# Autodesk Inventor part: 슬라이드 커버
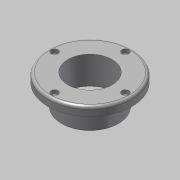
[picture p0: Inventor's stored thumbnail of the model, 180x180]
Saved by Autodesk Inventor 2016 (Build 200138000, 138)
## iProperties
Created: 2015-10
Part Number: 슬라이드 커버
Document SubType Name: Modeling
Designer: mdu
Density: 7.86 g/cm^3
Material: 강철, 연강
Mass: 633.012 g
Surface Area: 239.629 cm^2
Volume: 80.5358 cm^3
Appearance: 강철
Author: mdu
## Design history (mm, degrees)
sketch "스케치1"
  geometry: C1 r 47.5 at (0, 0); C2 r 32.5 at (0, 0); 1 further point
  constraints: 2 centre point, 2 coincident
  dimensions: "d33" = 95 diameter of C1; "d35" = 65 diameter of C2
extrude "돌출1" new body sketch "스케치1" distance "d0" = 10; taper "d1" = 0 deg
extrude "돌출2" join sketch "스케치1" distance "d2" = 25; taper "d3" = 0 deg
hole "구멍1" diameter "d6" = 50; stored, may be unused: countersink angle "d10" = 90 deg, drill point angle "d12" = 118 deg; dims "d4" = 10, "d5" = 10, "d7" = 6, "d8" = 4, "d9" = 2, "d11" = 8
sketch "스케치2" dims "d36" = 80
  geometry: 4 further points
  constraints: 2 coincident, 2 vertical alignment, 2 other
hole "구멍2" sketch "스케치2" at (0, 40) diameter "d13" = 4.5; stored, may be unused: countersink angle "d17" = 90 deg, drill point angle "d19" = 118 deg; dims "d14" = 6, "d15" = 8, "d16" = 4.4, "d18" = 8
fillet "모깎기1" dims "d23" = 3
chamfer "모따기1" distance "d24" = 1; stored, may be unused: second distance "d25" = 2, angle "d26" = 45 deg
sketch "스케치3"
  geometry: C1 r 25 at (0, 0); C2 r 30 at (0, 0); C3 r 26 at (0, 0) reference; 1 further point
  constraints: 2 centre point, 2 coincident
  dimensions: "d27" = 60 diameter of C2
extrude "돌출3" cut sketch "스케치3" distance "d28" = 3; taper "d29" = 0 deg
chamfer "모따기2" distance "d30" = 1; stored, may be unused: second distance "d31" = 2, angle "d32" = 45 deg
node "솔리드1"
pattern_circular "원형 패턴1" dims angle "d21" = 360 deg
